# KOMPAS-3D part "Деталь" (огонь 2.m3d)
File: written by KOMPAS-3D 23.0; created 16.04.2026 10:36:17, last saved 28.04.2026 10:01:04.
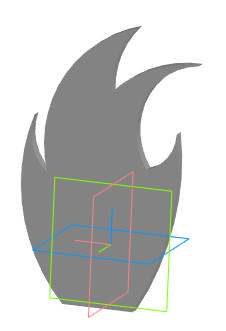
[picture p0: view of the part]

Document properties: Автор: USER; Полное имя файла: C:\Users\USER\Desktop\огонь 2.m3d

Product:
- Part/product: Деталь
    Масса: 0.202548

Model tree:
1. Эскиз:3
2. Элемент выдавливания:1
     Расстояние 1 = 5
